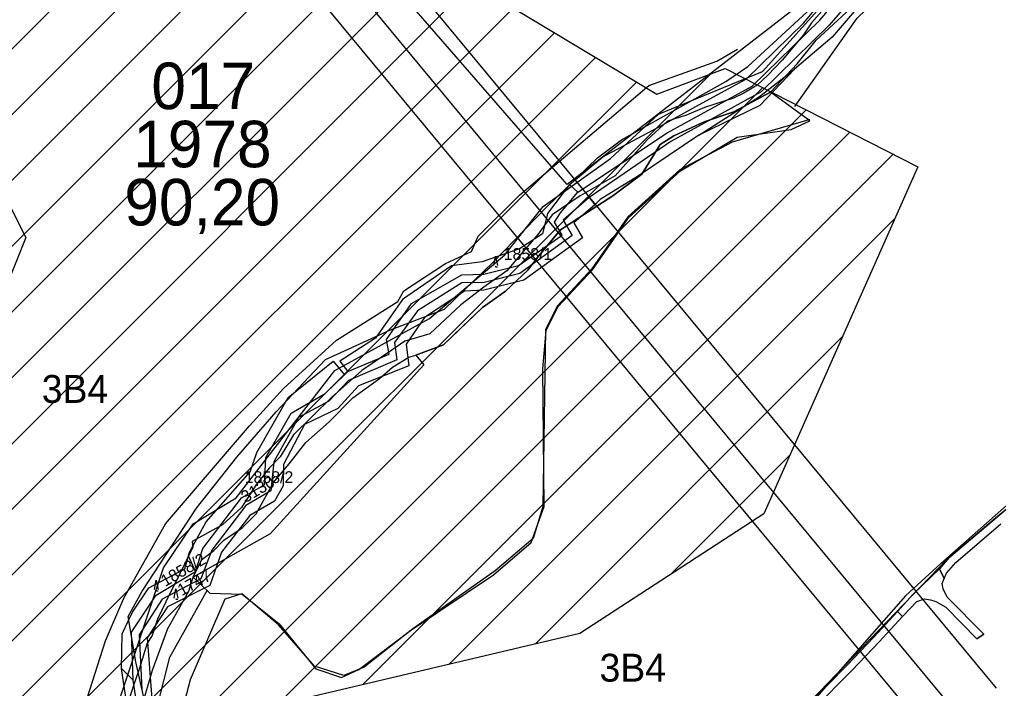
# Model space of a CAD drawing. Extents: x -564810 to -550519, y -1045831 to -1034011.
# Drawn here: x -552722.7 to -552301.9, y -1038878.7 to -1038591.1 of the extents above; entities that cross this region are included whole.
import ezdxf

# ---------------------------------------------------------------- set-up
doc = ezdxf.new("R2010")
doc.units = 0
for name, color, linetype in [('Biokoridory', 7, 'Continuous'), ('Interakční prvky', 7, 'Continuous'), ('KN stav', 7, 'Continuous'), ('Lesní porost', 7, 'Continuous'), ('Obvod KPU', 7, 'Continuous'), ('Odvodněné plochy', 7, 'Continuous'), ('Parcelní čísla', 7, 'Continuous'), ('Plynovod', 7, 'Continuous'), ('Polní cesty stavající', 7, 'Continuous'), ('přeložka st silnice', 7, 'Continuous'), ('STG', 7, 'Continuous'), ('Vedení VN', 7, 'Continuous'), ('vodní toky', 7, 'Continuous'), ('Vrstva 33', 7, 'Continuous'), ('Vrstva 4', 7, 'Continuous'), ('zamokř ploch', 7, 'Continuous')]:
    doc.layers.add(name, color=color, linetype=linetype)

msp = doc.modelspace()

# ---------------------------------------------------------------- linework, layer by layer
at = {"layer": 'Biokoridory'}
for points in [[(-552601.82, -1038534.57), (-552585.27, -1038532.38), (-552474.12, -1038448.63), (-552396.06, -1038375.14), (-552306.69, -1038448.63), (-552341.63, -1038491.89), (-552358.26, -1038532.37), (-552374.16, -1038574.42), (-552487.19, -1038662.04), (-552597.05, -1038535.55)], [(-552693.54, -1038882.9), (-552685.68, -1038858.26), (-552677.83, -1038839.89), (-552659.94, -1038807.87), (-552623.85, -1038765.73), (-552609.26, -1038749.75), (-552586.37, -1038728.9), (-552560.02, -1038712.36), (-552557.42, -1038707.69), (-552539.51, -1038695.96), (-552528.43, -1038690.85), (-552525.46, -1038684.26), (-552507.54, -1038666.39), (-552452.2, -1038619.48), (-552422.96, -1038608.93), (-552413.96, -1038603.79)], [(-552383.18, -1038633.88), (-552383.3, -1038634.15), (-552416.36, -1038643.85), (-552438.75, -1038655.74), (-552461.15, -1038675.97), (-552476.64, -1038698.23), (-552491.36, -1038714.1), (-552496.51, -1038724.37), (-552497.78, -1038800.43), (-552501.83, -1038814.28), (-552518.25, -1038828.14), (-552553.63, -1038853.08), (-552574.53, -1038869.5), (-552583.27, -1038873.12), (-552595.84, -1038869.07), (-552611.41, -1038851.38), (-552627.18, -1038837.95), (-552634.42, -1038840.29), (-552649.29, -1038875), (-552661.72, -1038921.93)]]:
    msp.add_lwpolyline(points, dxfattribs=at)
at = {"layer": 'Interakční prvky'}
for points in [[(-552888.79, -1039249.84), (-552870.94, -1039193.46), (-552864.8, -1039178.94), (-552852.52, -1039170.01), (-552839.13, -1039166.1), (-552811.23, -1039127.58), (-552777.19, -1039111.39), (-552753.76, -1039102.46), (-552722.66, -1039031.95), (-552707.03, -1039000.69), (-552684.15, -1038896.85), (-552660.81, -1038826.84), (-552647.98, -1038807.85), (-552629.57, -1038796.69), (-552587.16, -1038741.98), (-552546.42, -1038719.65), (-552514.06, -1038692.29), (-552497.58, -1038671.43), (-552468.56, -1038650.78), (-552447.92, -1038631.8), (-552403.28, -1038613.37), (-552369.24, -1038575.41), (-552351.38, -1038527.4)], [(-552389.33, -1038628.45), (-552362.54, -1038590.49), (-552343.57, -1038572.06), (-552335.76, -1038540.24)], [(-552873.92, -1039264.58), (-552857.18, -1039216.01), (-552845.46, -1039195.91), (-552826.49, -1039179.72), (-552814.22, -1039161.3), (-552789.66, -1039144.55), (-552774.04, -1039133.95), (-552742.23, -1039123.34), (-552732.19, -1039100.45), (-552727.73, -1039080.35), (-552709.31, -1039041.83), (-552692.57, -1039016.15), (-552670.3, -1038913.28), (-552658.03, -1038865.27), (-552641.85, -1038836.24)]]:
    msp.add_lwpolyline(points, dxfattribs=at)
at = {"layer": 'KN stav'}
for p, q in [((-552385.61, -1038592.59), (-552364.7, -1038567.68)), ((-552378.68, -1038591.39), (-552360.42, -1038569.72)), ((-552356.66, -1038572.44), (-552374.56, -1038593.55)), ((-552354.5, -1038576.66), (-552373.4, -1038598.6)), ((-552410.18, -1038616.51), (-552385.61, -1038592.59)), ((-552407.71, -1038619.72), (-552378.68, -1038591.39)), ((-552374.56, -1038593.55), (-552403.79, -1038622.17)), ((-552373.4, -1038598.6), (-552389.55, -1038612.43)), ((-552389.55, -1038612.43), (-552404.44, -1038628)), ((-552431.98, -1038628.51), (-552410.18, -1038616.51)), ((-552444.32, -1038639.75), (-552407.71, -1038619.72)), ((-552403.79, -1038622.17), (-552442.68, -1038643.46)), ((-552446.46, -1038636.47), (-552431.98, -1038628.51)), ((-552404.44, -1038628), (-552430.63, -1038640.83)), ((-552471.87, -1038650.13), (-552446.46, -1038636.47)), ((-552482.62, -1038665.27), (-552444.32, -1038639.75)), ((-552430.63, -1038640.83), (-552457.04, -1038658.5)), ((-552442.68, -1038643.46), (-552477.85, -1038667.56)), ((-552486.19, -1038661.93), (-552471.87, -1038650.13)), ((-552457.04, -1038658.5), (-552473.07, -1038668.48)), ((-552486.19, -1038661.93), (-552495.7, -1038674.43)), ((-552490.07, -1038674.21), (-552482.62, -1038665.27)), ((-552477.85, -1038667.56), (-552488.95, -1038677.34)), ((-552473.07, -1038668.48), (-552475.42, -1038670.69)), ((-552475.42, -1038670.69), (-552484.4, -1038678.49)), ((-552495.7, -1038674.43), (-552497.84, -1038683.2)), ((-552492.67, -1038678.18), (-552490.07, -1038674.21)), ((-552489.45, -1038683.73), (-552492.67, -1038678.18)), ((-552488.95, -1038677.34), (-552485.16, -1038683.88)), ((-552484.4, -1038678.49), (-552480.64, -1038684.98)), ((-552508.24, -1038696.89), (-552489.45, -1038683.73)), ((-552497.84, -1038683.2), (-552507.76, -1038689.7)), ((-552485.16, -1038683.88), (-552507.66, -1038700.22)), ((-552480.64, -1038684.98), (-552505.94, -1038703.15)), ((-552507.76, -1038689.7), (-552523.73, -1038695.31)), ((-552537.03, -1038696.98), (-552558.1, -1038711.46)), ((-552523.73, -1038695.31), (-552537.03, -1038696.98)), ((-552523.05, -1038700.58), (-552508.24, -1038696.89)), ((-552554.16, -1038713.18), (-552532.6, -1038700.78)), ((-552532.6, -1038700.78), (-552523.05, -1038700.58)), ((-552507.66, -1038700.22), (-552522.98, -1038704.15)), ((-552532.52, -1038704.35), (-552551.55, -1038716.36)), ((-552522.98, -1038704.15), (-552532.52, -1038704.35)), ((-552505.94, -1038703.15), (-552523.01, -1038707.46)), ((-552531.46, -1038707.81), (-552548.56, -1038719.24)), ((-552523.01, -1038707.46), (-552531.46, -1038707.81)), ((-552558.1, -1038711.46), (-552569.64, -1038728.11)), ((-552564.97, -1038728.67), (-552554.16, -1038713.18)), ((-552551.55, -1038716.36), (-552561.54, -1038729.92)), ((-552548.56, -1038719.24), (-552556.47, -1038730.65)), ((-552569.64, -1038728.11), (-552584.93, -1038738.03)), ((-552563.78, -1038735), (-552564.97, -1038728.67)), ((-552561.54, -1038729.92), (-552560.55, -1038737.37)), ((-552556.47, -1038730.65), (-552555.3, -1038739.9)), ((-552581.51, -1038742.45), (-552563.78, -1038735)), ((-552607.21, -1038753.59), (-552587.91, -1038737.9)), ((-552587.91, -1038737.9), (-552582.96, -1038743.84)), ((-552584.93, -1038738.03), (-552581.51, -1038742.45)), ((-552560.55, -1038737.37), (-552581.24, -1038746.34)), ((-552555.3, -1038739.9), (-552577.03, -1038748.64)), ((-552591.33, -1038751.88), (-552582.96, -1038743.84)), ((-552582.96, -1038743.84), (-552581.51, -1038742.45)), ((-552581.24, -1038746.34), (-552589.73, -1038755.18)), ((-552605.96, -1038760.38), (-552591.33, -1038751.88)), ((-552577.03, -1038748.64), (-552585.87, -1038758.27)), ((-552620.63, -1038777.19), (-552607.21, -1038753.59)), ((-552589.73, -1038755.18), (-552602.73, -1038762.23)), ((-552616.79, -1038779.45), (-552605.96, -1038760.38)), ((-552585.87, -1038758.27), (-552600.16, -1038765.13)), ((-552253.02, -1038759.94), (-552326.68, -1038824.98)), ((-552602.73, -1038762.23), (-552613.29, -1038781.2)), ((-552600.16, -1038765.13), (-552609.22, -1038782.39)), ((-552623.51, -1038785.51), (-552620.63, -1038777.19)), ((-552617.35, -1038791.16), (-552616.79, -1038779.45)), ((-552613.29, -1038781.2), (-552614.64, -1038793.7)), ((-552642.38, -1038807.05), (-552623.51, -1038785.51)), ((-552609.22, -1038782.39), (-552609.39, -1038791.56)), ((-552627.29, -1038796.76), (-552617.35, -1038791.16)), ((-552614.64, -1038793.7), (-552625.43, -1038800.09)), ((-552609.39, -1038791.56), (-552613.06, -1038798.17)), ((-552643.92, -1038818.53), (-552627.29, -1038796.76)), ((-552613.06, -1038798.17), (-552623.74, -1038804.33)), ((-552625.43, -1038800.09), (-552640.02, -1038819.26)), ((-552649.68, -1038820.16), (-552642.38, -1038807.05)), ((-552623.74, -1038804.33), (-552635.84, -1038820.16)), ((-552647.03, -1038828.36), (-552643.92, -1038818.53)), ((-552640.02, -1038819.26), (-552644.74, -1038831.52)), ((-552651.61, -1038827.28), (-552650.52, -1038823.27)), ((-552650.52, -1038823.27), (-552649.68, -1038820.16)), ((-552635.84, -1038820.16), (-552640.92, -1038834.41)), ((-552667.09, -1038835.42), (-552651.61, -1038827.28)), ((-552663.92, -1038838.53), (-552647.03, -1038828.36)), ((-552326.68, -1038824.98), (-552341.81, -1038838.89)), ((-552644.74, -1038831.52), (-552661.32, -1038840.34)), ((-552674.1, -1038845.93), (-552667.09, -1038835.42)), ((-552640.92, -1038834.41), (-552659.12, -1038843.62)), ((-552674.49, -1038854.52), (-552663.92, -1038838.53)), ((-552661.32, -1038840.34), (-552671.27, -1038855.65)), ((-552341.81, -1038838.89), (-552385.85, -1038888.91)), ((-552659.12, -1038843.62), (-552667.88, -1038856.9)), ((-552675.94, -1038849.81), (-552674.1, -1038845.93)), ((-552678.5, -1038855.2), (-552675.94, -1038849.81)), ((-552678.9, -1038870.11), (-552678.5, -1038855.2)), ((-552673.87, -1038875.09), (-552674.49, -1038854.52)), ((-552671.27, -1038855.65), (-552670.14, -1038879.21)), ((-552667.88, -1038856.9), (-552665.83, -1038883.18)), ((-552675.22, -1038894.13), (-552678.9, -1038870.11)), ((-552670.81, -1038894.7), (-552673.87, -1038875.09))]:
    msp.add_line(p, q, dxfattribs=at)
at = {"layer": 'Lesní porost'}
for p, q in [((-552399.79, -1038622.34), (-552415.62, -1038630.78)), ((-552382.94, -1038634.59), (-552399.79, -1038622.34)), ((-552415.62, -1038630.78), (-552428.41, -1038635.02)), ((-552391.02, -1038638.32), (-552382.94, -1038634.59)), ((-552428.41, -1038635.02), (-552441.37, -1038641.07)), ((-552414.12, -1038641.58), (-552391.02, -1038638.32)), ((-552441.37, -1038641.07), (-552447.23, -1038644.77)), ((-552438.53, -1038656.16), (-552414.12, -1038641.58)), ((-552447.23, -1038644.77), (-552455.15, -1038657.6)), ((-552455.15, -1038657.6), (-552467.61, -1038666.9)), ((-552460.93, -1038676.39), (-552438.53, -1038656.16)), ((-552467.61, -1038666.9), (-552478.52, -1038673.88)), ((-552478.52, -1038673.88), (-552490.06, -1038681.5)), ((-552476.42, -1038698.65), (-552460.93, -1038676.39)), ((-552490.06, -1038681.5), (-552500.29, -1038693.7)), ((-552500.29, -1038693.7), (-552504.14, -1038698.81)), ((-552504.14, -1038698.81), (-552513.74, -1038707.91)), ((-552491.14, -1038714.52), (-552476.42, -1038698.65)), ((-552516.48, -1038709.85), (-552523.65, -1038714.91)), ((-552516.22, -1038709.88), (-552516.48, -1038709.85)), ((-552516.2, -1038709.64), (-552516.22, -1038709.88)), ((-552513.74, -1038707.91), (-552516.2, -1038709.64)), ((-552496.29, -1038724.79), (-552491.14, -1038714.52)), ((-552523.65, -1038714.91), (-552529.25, -1038720.23)), ((-552532.27, -1038723.1), (-552540.46, -1038730.88)), ((-552529.39, -1038720.36), (-552532.27, -1038723.1)), ((-552529.26, -1038720.37), (-552529.39, -1038720.36)), ((-552529.25, -1038720.23), (-552529.26, -1038720.37)), ((-552497.74, -1038741.33), (-552496.29, -1038724.79)), ((-552540.46, -1038730.88), (-552552.33, -1038735.44)), ((-552552.33, -1038735.44), (-552548.94, -1038739.6)), ((-552548.94, -1038739.6), (-552614.99, -1038812.27)), ((-552497.2, -1038800.5), (-552497.74, -1038741.33)), ((-552502.66, -1038815.91), (-552497.2, -1038800.5)), ((-552614.99, -1038812.27), (-552648, -1038830.81)), ((-552518.94, -1038829.81), (-552502.66, -1038815.91)), ((-552648, -1038830.81), (-552640.87, -1038837.73)), ((-552648, -1038830.81), (-552640.87, -1038837.73)), ((-552554.64, -1038853.82), (-552518.94, -1038829.81)), ((-552640.87, -1038837.73), (-552627.02, -1038838.11)), ((-552627.02, -1038838.11), (-552611.12, -1038850.91)), ((-552611.12, -1038850.91), (-552595.33, -1038870.22)), ((-552576.85, -1038870.49), (-552554.64, -1038853.82)), ((-552595.33, -1038870.22), (-552584.22, -1038874.01)), ((-552584.22, -1038874.01), (-552576.85, -1038870.49))]:
    msp.add_line(p, q, dxfattribs=at)
at = {"layer": 'Obvod KPU'}
for p, q in [((-552324.24, -1038823.4), (-552240.29, -1038752.09)), ((-552386.15, -1038887.74), (-552324.24, -1038823.4))]:
    msp.add_line(p, q, dxfattribs=at)
at = {"layer": 'Odvodněné plochy'}
msp.add_lwpolyline([(-551989.93, -1038520.85), (-552018.66, -1038556.91), (-552029.84, -1038571.81), (-552082.19, -1038617.68), (-552111.93, -1038645.23), (-552181.86, -1038619.46), (-552301.49, -1038551.35), (-552386.14, -1038496.12), (-552459.76, -1038429.85), (-552553.61, -1038538.46), (-552513.13, -1038584.48), (-552448.71, -1038623.14), (-552419.27, -1038612.1), (-552336.45, -1038654.44), (-552402.71, -1038803.54), (-552481.84, -1038855.09), (-552606.98, -1038884.54)], dxfattribs=at)
at = {"layer": 'Plynovod'}
for points in [[(-554428.56, -1035578.55), (-554428.56, -1035578.55), (-554428.56, -1035578.55), (-554027.79, -1036081.22), (-553723.76, -1036467.01), (-553550.38, -1036705.78), (-553550.38, -1036705.78), (-553522.74, -1037110.43), (-553438.57, -1037242.38), (-553213.69, -1037591.73), (-553193.58, -1037703.57), (-553145.84, -1037777.72), (-553110.67, -1037838.04), (-552972.47, -1038070.52), (-552972.47, -1038070.52), (-552302.85, -1038878.56)], [(-552322.24, -1038886.46), (-552991.86, -1038078.43), (-553130.06, -1037845.94), (-553165.24, -1037785.62), (-553212.98, -1037711.48), (-553233.08, -1037599.64), (-553457.96, -1037250.28), (-553542.14, -1037118.33), (-553569.78, -1036713.69), (-553743.15, -1036474.92), (-554047.18, -1036089.12), (-554447.95, -1035586.45)], [(-552330.5, -1038899.71), (-553000.12, -1038091.67), (-553138.32, -1037859.19), (-553173.5, -1037798.87), (-553221.24, -1037724.72), (-553241.34, -1037612.88), (-553466.22, -1037263.53), (-553550.4, -1037131.58), (-553578.03, -1036726.93), (-553751.41, -1036488.16), (-554055.44, -1036102.37), (-554456.21, -1035599.7)]]:
    msp.add_lwpolyline(points, dxfattribs=at)
at = {"layer": 'Polní cesty stavající'}
for p, q in [((-552271.22, -1038779.36), (-552303.08, -1038805.42)), ((-552303.08, -1038805.42), (-552322.98, -1038822.42)), ((-552320.15, -1038824.53), (-552300.87, -1038807.89)), ((-552322.98, -1038822.42), (-552327.26, -1038827.2)), ((-552327.26, -1038827.2), (-552338.45, -1038838.14)), ((-552325.19, -1038831.4), (-552327.26, -1038827.2)), ((-552327.26, -1038827.2), (-552325.19, -1038831.4)), ((-552324.14, -1038829.1), (-552320.15, -1038824.53)), ((-552326.1, -1038833.53), (-552325.19, -1038831.4)), ((-552325.19, -1038831.4), (-552324.14, -1038829.1)), ((-552325.67, -1038835.88), (-552326.1, -1038833.53)), ((-552323.83, -1038839.39), (-552325.67, -1038835.88)), ((-552338.45, -1038838.14), (-552345.21, -1038845.61)), ((-552336.99, -1038841.28), (-552333.63, -1038840.16)), ((-552333.63, -1038840.16), (-552331.05, -1038840.56)), ((-552331.05, -1038840.56), (-552328.7, -1038841.28)), ((-552308.06, -1038855.41), (-552323.83, -1038839.39)), ((-552343.06, -1038847.77), (-552336.99, -1038841.28)), ((-552328.7, -1038841.28), (-552324.51, -1038843.74)), ((-552324.51, -1038843.74), (-552311.09, -1038857.4)), ((-552345.21, -1038845.61), (-552355.49, -1038856.63)), ((-552353.17, -1038858.7), (-552343.06, -1038847.77)), ((-552343.06, -1038847.77), (-552345.21, -1038845.61)), ((-552345.21, -1038845.61), (-552343.06, -1038847.77)), ((-552355.49, -1038856.63), (-552366.93, -1038868.61)), ((-552308.06, -1038855.41), (-552311.09, -1038857.4)), ((-552311.09, -1038857.4), (-552308.06, -1038855.41)), ((-552364.73, -1038870.84), (-552353.17, -1038858.7)), ((-552366.93, -1038868.61), (-552383.34, -1038885.4)), ((-552381.57, -1038887.8), (-552364.73, -1038870.84))]:
    msp.add_line(p, q, dxfattribs=at)
at = {"layer": 'přeložka st silnice'}
for p, q in [((-552988.3, -1038866.01), (-551899.29, -1037777)), ((-552896.76, -1038802.75), (-551890.75, -1037796.74)), ((-552878.46, -1038812.73), (-551882.2, -1037816.47)), ((-552860.16, -1038822.72), (-551871.31, -1037833.87)), ((-552841.86, -1038832.7), (-552550.81, -1038541.65)), ((-552823.56, -1038842.69), (-552537.57, -1038556.7)), ((-552805.26, -1038852.67), (-552524.33, -1038571.75)), ((-552786.96, -1038862.66), (-552510.41, -1038586.11)), ((-552768.66, -1038872.64), (-552492.74, -1038596.72)), ((-552758.93, -1038891.19), (-552475.06, -1038607.33)), ((-552750, -1038910.55), (-552457.39, -1038617.94)), ((-552741.07, -1038929.9), (-552425.66, -1038614.49)), ((-552731.46, -1038948.58), (-552403.2, -1038620.31)), ((-552719.22, -1038964.62), (-552384.48, -1038629.88)), ((-552706.98, -1038980.66), (-552365.76, -1038639.45)), ((-552575.05, -1038877.02), (-552347.05, -1038649.02)), ((-552538.06, -1038868.32), (-552346.27, -1038676.52)), ((-552501.07, -1038859.61), (-552368.88, -1038727.42)), ((-552442.9, -1038829.72), (-552391.5, -1038778.32))]:
    msp.add_line(p, q, dxfattribs=at)
at = {"layer": 'Vedení VN'}
msp.add_lwpolyline([(-552789.04, -1038682.17), (-552763.05, -1038666.89), (-552748.3, -1038659.52), (-552733.86, -1038657.44), (-552719.92, -1038684.84), (-552739.28, -1038732.83), (-552746.47, -1038733.96), (-552761.72, -1038729.89)], close=True, dxfattribs=at)
at = {"layer": 'vodní toky'}
for p, q in [((-552377.74, -1038587.51), (-552382.25, -1038592.52)), ((-552380.22, -1038599.88), (-552363.58, -1038584.6)), ((-552382.25, -1038592.52), (-552385.65, -1038597.66)), ((-552385.65, -1038597.66), (-552394.79, -1038608.57)), ((-552388.42, -1038610.16), (-552380.22, -1038599.88)), ((-552394.79, -1038608.57), (-552401, -1038614.95)), ((-552399.79, -1038622.34), (-552388.42, -1038610.16)), ((-552401, -1038614.95), (-552405.57, -1038619.31)), ((-552405.57, -1038619.31), (-552411.29, -1038622.67)), ((-552419.8, -1038626.11), (-552428.19, -1038628.83)), ((-552415.72, -1038624.82), (-552419.8, -1038626.11)), ((-552411.29, -1038622.67), (-552415.72, -1038624.82)), ((-552415.62, -1038630.78), (-552399.79, -1038622.34)), ((-552428.19, -1038628.83), (-552435.9, -1038632.19)), ((-552444.11, -1038634.79), (-552452.83, -1038642.8)), ((-552435.9, -1038632.19), (-552444.11, -1038634.79)), ((-552428.41, -1038635.02), (-552415.62, -1038630.78)), ((-552441.37, -1038641.07), (-552428.41, -1038635.02)), ((-552452.83, -1038642.8), (-552466.63, -1038658.3)), ((-552447.23, -1038644.77), (-552441.37, -1038641.07)), ((-552455.15, -1038657.6), (-552447.23, -1038644.77)), ((-552466.63, -1038658.3), (-552481.7, -1038666.9)), ((-552467.61, -1038666.9), (-552455.15, -1038657.6)), ((-552481.7, -1038666.9), (-552493.64, -1038675.01)), ((-552478.52, -1038673.88), (-552467.61, -1038666.9)), ((-552493.64, -1038675.01), (-552499.93, -1038683.52)), ((-552490.06, -1038681.5), (-552478.52, -1038673.88)), ((-552499.93, -1038683.52), (-552506.15, -1038690.79)), ((-552500.29, -1038693.7), (-552490.06, -1038681.5)), ((-552506.15, -1038690.79), (-552513.14, -1038699.08)), ((-552504.14, -1038698.81), (-552500.29, -1038693.7)), ((-552513.14, -1038699.08), (-552523.07, -1038706.11)), ((-552513.74, -1038707.91), (-552504.14, -1038698.81)), ((-552523.07, -1038706.11), (-552533.03, -1038713.77)), ((-552523.65, -1038714.91), (-552513.74, -1038707.91)), ((-552533.03, -1038713.77), (-552546.27, -1038726.18)), ((-552540.46, -1038730.88), (-552523.65, -1038714.91)), ((-552546.27, -1038726.18), (-552556.98, -1038729.41)), ((-552556.98, -1038729.41), (-552562.61, -1038733.3)), ((-552552.33, -1038735.44), (-552540.46, -1038730.88)), ((-552562.61, -1038733.3), (-552575.55, -1038742.01)), ((-552555.3, -1038736.21), (-552552.33, -1038735.44)), ((-552562.28, -1038740.48), (-552555.3, -1038736.21)), ((-552575.55, -1038742.01), (-552588.59, -1038753.56)), ((-552567.98, -1038745.36), (-552562.28, -1038740.48)), ((-552579.44, -1038753.75), (-552567.98, -1038745.36)), ((-552588.59, -1038753.56), (-552604.87, -1038769.62)), ((-552589.62, -1038764.03), (-552579.44, -1038753.75)), ((-552599.65, -1038772.98), (-552589.62, -1038764.03)), ((-552604.87, -1038769.62), (-552610.64, -1038779.14)), ((-552606.72, -1038782.12), (-552599.65, -1038772.98)), ((-552610.64, -1038779.14), (-552615.35, -1038783.97)), ((-552615.35, -1038783.97), (-552620.84, -1038790.91)), ((-552613.53, -1038790.07), (-552606.72, -1038782.12)), ((-552621.01, -1038803.57), (-552613.53, -1038790.07)), ((-552620.84, -1038790.91), (-552627.29, -1038800.88)), ((-552627.29, -1038800.88), (-552635.46, -1038808.35)), ((-552626.95, -1038809.69), (-552621.01, -1038803.57)), ((-552635.46, -1038808.35), (-552648.43, -1038815.55)), ((-552634.89, -1038814.97), (-552626.95, -1038809.69)), ((-552648.43, -1038815.55), (-552648.23, -1038818)), ((-552639.16, -1038819.43), (-552634.89, -1038814.97)), ((-552648.23, -1038818), (-552653.19, -1038828.25)), ((-552644.24, -1038823.19), (-552639.16, -1038819.43)), ((-552648, -1038830.81), (-552644.24, -1038823.19)), ((-552653.19, -1038828.25), (-552657.89, -1038837.53)), ((-552649.83, -1038836.84), (-552648, -1038830.81)), ((-552657.89, -1038837.53), (-552663.32, -1038848.83)), ((-552658.99, -1038852.98), (-552649.83, -1038836.84)), ((-552663.32, -1038848.83), (-552665.69, -1038855.9)), ((-552665.49, -1038870.76), (-552658.99, -1038852.98)), ((-552665.69, -1038855.9), (-552667.74, -1038859.22)), ((-552667.74, -1038859.22), (-552671.1, -1038869.96)), ((-552671.1, -1038869.96), (-552673.77, -1038877.89)), ((-552670, -1038885.99), (-552665.49, -1038870.76)), ((-552673.77, -1038877.89), (-552678.35, -1038891.9))]:
    msp.add_line(p, q, dxfattribs=at)
at = {"layer": 'Vrstva 33'}
msp.add_lwpolyline([(-552669.2, -1038882.52), (-552672.73, -1038867.19), (-552675.91, -1038847.76), (-552669.91, -1038836.8), (-552646.6, -1038801.12), (-552629.3, -1038779.22), (-552612.35, -1038759.79), (-552591.16, -1038737.18), (-552563.27, -1038724.46), (-552539.96, -1038715.63), (-552519.02, -1038695.38), (-552496.07, -1038671.71), (-552474.18, -1038650.52), (-552463.94, -1038642.75), (-552419.09, -1038617.66), (-552409.56, -1038611.3), (-552382.37, -1038586.22)], dxfattribs=at)
at = {"layer": 'Vrstva 4'}
for p, q in [((-552404.58, -1038624.21), (-552389.55, -1038612.43)), ((-552430.63, -1038640.83), (-552404.58, -1038624.21)), ((-552486.19, -1038661.93), (-552482.62, -1038665.27)), ((-552477.85, -1038667.56), (-552475.42, -1038670.69)), ((-552647.03, -1038828.36), (-552650.09, -1038821.67)), ((-552678.9, -1038870.11), (-552673.87, -1038875.09))]:
    msp.add_line(p, q, dxfattribs=at)
at = {"layer": 'zamokř ploch'}
for points in [[(-552518.72, -1038696.87), (-552518.02, -1038692.87), (-552517.22, -1038696.87)], [(-552518.02, -1038697.17), (-552518.02, -1038697.37), (-552517.22, -1038697.37)], [(-552664.64, -1038836.2), (-552663.94, -1038832.2), (-552663.14, -1038836.2)], [(-552663.94, -1038836.5), (-552663.94, -1038836.7), (-552663.14, -1038836.7)], [(-552656.14, -1038839.85), (-552655.44, -1038835.85), (-552654.64, -1038839.85)], [(-552655.44, -1038840.15), (-552655.44, -1038840.35), (-552654.64, -1038840.35)]]:
    msp.add_lwpolyline(points, dxfattribs=at)

# ---------------------------------------------------------------- texts
at = {"layer": 'Odvodněné plochy'}
for s, p in [('017', (-552666.01, -1038629.6)), ('1978', (-552673.8, -1038654.6)), ('90,20', (-552677.62, -1038679.6))]:
    msp.add_text(s, height=20, dxfattribs=at).set_placement(p)
at = {"layer": 'Parcelní čísla'}
for s, p in [('1858/1', (-552514.52, -1038694.45)), ('1858/2', (-552625.86, -1038790.39))]:
    msp.add_text(s, height=5.1, dxfattribs=at).set_placement(p)
for s, rotation, p in [('3130', 30.283, (-552625.55, -1038799.04)), ('1858/2', 30.0302, (-552660.08, -1038835.1)), ('1747', 28.7783, (-552652.98, -1038839.08))]:
    msp.add_text(s, height=5.1, rotation=rotation, dxfattribs=at).set_placement(p)
at = {"layer": 'STG'}
for p in [(-552713.13, -1038755.91), (-552473.33, -1038875.77)]:
    msp.add_text('3B4', height=12, dxfattribs=at).set_placement(p)

doc.saveas('drawing.dxf')
